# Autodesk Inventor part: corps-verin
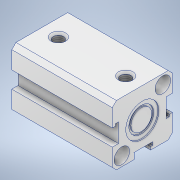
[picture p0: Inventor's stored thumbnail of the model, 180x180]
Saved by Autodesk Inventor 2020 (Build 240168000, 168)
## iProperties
Created: 2023-10
Part Number: corps-verin
Material: Aluminium 6061
Document SubType Name: Modeling
Designer: bruno
Density: 2.7 g/cm^3
Appearance: Aluminium - Plat
Author: bruno
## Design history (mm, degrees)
sketch "Esquisse1"
  geometry: L1 (0, 0)-(29, 0); L2 (29, 0)-(29, -29); L3 (10.5, -29)-(10.5, -27.5); L4 (18.5, -27)-(18.5, -29); L5 (10.5, -27.5)-(9.454, -27.5); L6 (9.454, -27.5)-(9.454, -26); L7 (9.454, -26)-(18.5, -26); L8 (18.5, -26)-(18.5, -27); L9 (0, -29)-(29, 0); L10 (0, -18.5)-(1.5, -18.5); L11 (2, -10.5)-(0, -10.5); L12 (1.5, -18.5)-(1.5, -19.546); L13 (1.5, -19.546)-(3, -19.546); L14 (3, -19.546)-(3, -10.5); L15 (3, -10.5)-(2, -10.5); L16 (0, 0)-(29, -29); L17 (29, -29)-(18.5, -29); L18 (10.5, -29)-(0, -29); L19 (0, -29)-(0, -18.5); L20 (0, -10.5)-(0, 0); L21 (19.546, -1.5)-(19.546, -3); L22 (18.5, -1.5)-(19.546, -1.5); L23 (18.5, 0)-(18.5, -1.5); L24 (19.546, -3)-(10.5, -3); L25 (10.5, -3)-(10.5, -2); L26 (10.5, -2)-(10.5, 0); C1 r 2 at (24.404, -24.404); C2 r 2 at (4.605, -4.605); 2 further points
  constraints: 52 end point, 14 symmetric about line, 7 parallel, 2 centre point, 2 horizontal, 2 perpendicular, 2 point on line
  dimensions: "d0" = 29 distance of L2.end L9.start; "d1" = 29 distance of L1.end L2.end; "d2" = 10.5 distance between parallel lines of L2 L4; "d6" = 1.5 distance between parallel lines of L18 L5; "d7" = 1.5 distance of L5.end L6.end; "d8" = 4 diameter of C1; "d9" = 4 diameter of C2; "d10" = 28 distance of C2.centre C1.centre; "d11" = 6.5 distance of L2.end C1.centre
extrude "Extrusion1" new body sketch "Esquisse1" distance "d12" = 48.5; taper "d13" = 0 deg
chamfer "Chanfrein1" distance "d14" = 2; stored, may be unused: second distance "d15" = 2, angle "d16" = 45 deg
sketch "Esquisse2"
  geometry: L1 (2, 29)-(0, 27) reference; L2 (1, 28)-(28, 1); L3 (27, 0)-(29, 2) reference; C1 r 8 at (14.5, 14.5); 1 further point
  constraints: 3 midpoint, 2 end point, 1 centre point
  dimensions: "d17" = 16 diameter of C1
extrude "Extrusion2" cut sketch "Esquisse2" distance "d18" = 0.5; taper "d19" = 0 deg
sketch "Esquisse3"
  geometry: C1 r 6 at (0, 0); C2 r 5 at (0, 0); 1 further point
  constraints: 2 centre point, 1 coincident
  dimensions: "d20" = 12 diameter of C1; "d21" = 10 diameter of C2
extrude "Extrusion3" cut sketch "Esquisse3" distance "d22" = 0.5; taper "d23" = 0 deg
sketch "Esquisse4"
  geometry: C1 r 2 at (4.605, 4.605) reference; C2 r 2 at (24.404, 24.404) reference; C3 r 3.75 at (24.404, 24.404); C4 r 3.75 at (4.605, 4.605); 1 further point
  constraints: 2 centre point, 2 coincident
  dimensions: "d24" = 7.5 diameter of C3; "d25" = 7.5 diameter of C4
extrude "Extrusion4" cut sketch "Esquisse4" distance "d26" = 6; taper "d27" = 0 deg
sketch "Esquisse5"
  geometry: C1 r 2 at (-24.404, 24.404) reference; C2 r 2 at (-4.605, 4.605) reference; C3 r 3.75 at (-24.404, 24.404) reference; C4 r 3.75 at (-4.605, 4.605) reference; 1 further point
extrude "Extrusion5" cut sketch "Esquisse5" distance "d28" = 6; taper "d29" = 0 deg
sketch "Esquisse6"
  geometry: L1 (-29, 27)-(-27, 29) reference; L2 (0, 2)-(-2, 0) reference; L3 (-28, 28)-(-1, 1); L4 (-2, 0)-(0, 2) reference; C1 r 9 at (-14.5, 14.5); C2 r 5.5 at (-14.5, 14.5); 1 further point
  constraints: 2 centre point, 2 end point, 2 midpoint, 1 coincident
  dimensions: "d30" = 18 diameter of C1; "d31" = 11 diameter of C2
extrude "Extrusion6" cut sketch "Esquisse6" distance "d32" = 4; taper "d33" = 0 deg
sketch "Esquisse7"
  geometry: C1 r 5.5 at (0, 0) reference; 1 further point
extrude "Extrusion7" join sketch "Esquisse7" distance "d34" = 2; taper "d35" = 0 deg
fillet "Congé1" dims "d36" = 0.5
chamfer "Chanfrein2" distance "d37" = 0.5; stored, may be unused: second distance "d38" = 2, angle "d39" = 45 deg
sketch "Esquisse8"
  geometry: C1 r 5 at (0, 0) reference; C2 r 3 at (0, 0); 1 further point
  constraints: 1 centre point, 1 coincident
  dimensions: "d40" = 6 diameter of C2
extrude "Extrusion8" cut sketch "Esquisse8" distance "d41" = 40; taper "d42" = 0 deg
sketch "Esquisse9"
  geometry: L1 (0, 25)-(0, 0) reference; L2 (48.5, 25)-(48.5, 0) reference; C1 r 2.5 at (8, 12.5); C2 r 2.5 at (40.5, 12.5); 1 further point
  constraints: 2 centre point
  dimensions: "d43" = 5 diameter of C1; "d44" = 8 distance from line of L1 C1.centre; "d45" = 5 diameter of C2; "d46" = 8 distance from line of C2.centre L2
extrude "Extrusion9" cut sketch "Esquisse9" distance "d47" = 10; taper "d48" = 0 deg
chamfer "Chanfrein3" distance "d49" = 1; stored, may be unused: second distance "d50" = 2, angle "d51" = 45 deg
feature "Filetage1" dims "d52" = 9, "d53" = 0
feature "Filetage2" dims "d54" = 9, "d55" = 0
feature "Filetage3" dims "d56" = 36.5, "d57" = 0
feature "Filetage4" dims "d58" = 36.5, "d59" = 0
node "Solide1"
node "Boucle projetée1"
other parameters: "d3" = 10.5, "d4" = 2
